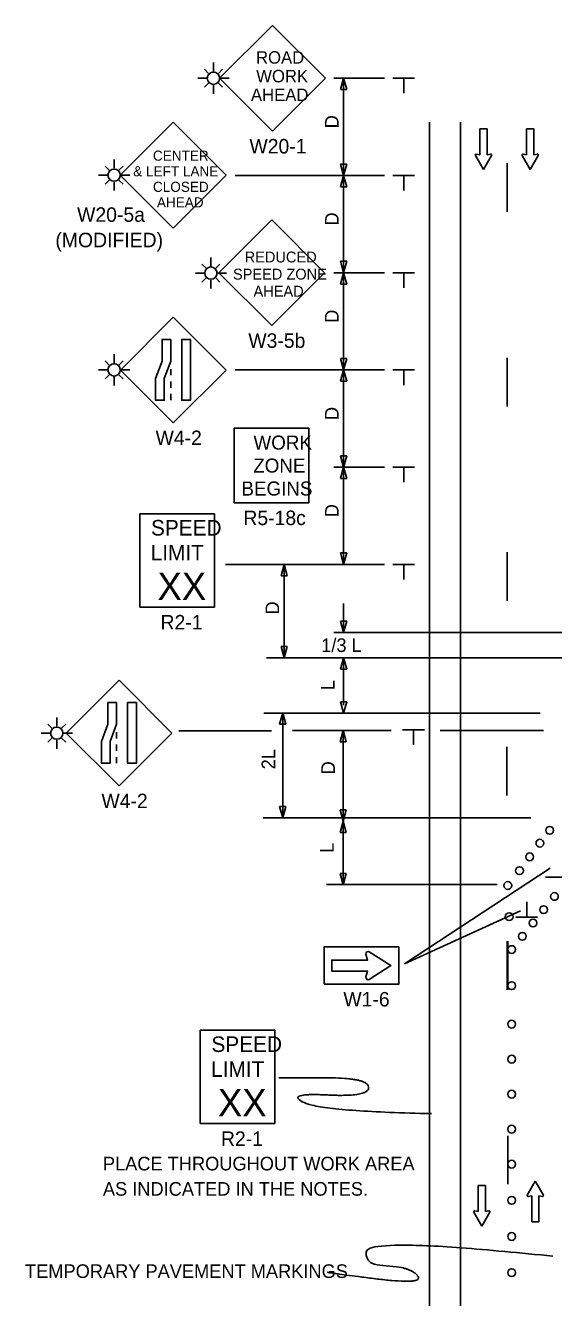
# Model space of a CAD drawing. Extents: x 16731 to 19504, y 5932 to 7446.
# Drawn here: x 16731 to 17002, y 6261 to 6915 of the extents above; entities that cross this region are included whole.
import ezdxf

# ---------------------------------------------------------------- set-up
doc = ezdxf.new("R2010")
doc.units = 0
for name, color, linetype in [('ALI_LEGAL_EX', 7, 'Continuous'), ('MT_SCRATCH_LEVEL_E', 7, 'Continuous'), ('PAVT_EDGE_EX', 7, 'Continuous'), ('TRAFFIC_SIGNS_PR', 7, 'Continuous'), ('TYPICAL_EX', 7, 'Continuous'), ('TYPICAL_TEXT_DIMEN_PR', 7, 'Continuous')]:
    doc.layers.add(name, color=color, linetype=linetype)

msp = doc.modelspace()

# ---------------------------------------------------------------- linework, layer by layer
at = {"layer": 'ALI_LEGAL_EX'}
for points in [[(16978.71, 6819.12), (16978.71, 6844.12)], [(16978.71, 6719.12), (16978.71, 6744.12)], [(16978.71, 6619.12), (16978.71, 6644.12)], [(16978.5, 6519.12), (16978.5, 6544.12)], [(16978.71, 6419.12), (16978.71, 6444.12)], [(16978.95, 6419.12), (16978.95, 6444.12)], [(16978.95, 6319.12), (16978.95, 6344.12)]]:
    msp.add_lwpolyline(points, dxfattribs=at)
at = {"layer": 'MT_SCRATCH_LEVEL_E'}
for p, q in [((16968.31, 6861.76), (16964.57, 6861.76)), ((16964.57, 6861.76), (16964.57, 6848.5)), ((16968.31, 6861.76), (16964.57, 6861.76)), ((16964.57, 6861.76), (16964.57, 6848.5)), ((16968.31, 6848.5), (16968.31, 6861.76)), ((16968.31, 6848.5), (16968.31, 6861.76)), ((16992.38, 6861.76), (16988.64, 6861.76)), ((16988.64, 6861.76), (16988.64, 6848.5)), ((16992.38, 6861.76), (16988.64, 6861.76)), ((16988.64, 6861.76), (16988.64, 6848.5)), ((16992.38, 6848.5), (16992.38, 6861.76)), ((16992.38, 6848.5), (16992.38, 6861.76)), ((16964.57, 6848.5), (16962.79, 6848.82)), ((16964.57, 6848.5), (16962.79, 6848.82)), ((16970.08, 6848.82), (16968.31, 6848.5)), ((16970.08, 6848.82), (16968.31, 6848.5)), ((16988.64, 6848.5), (16986.86, 6848.82)), ((16988.64, 6848.5), (16986.86, 6848.82)), ((16994.16, 6848.82), (16992.38, 6848.5)), ((16994.16, 6848.82), (16992.38, 6848.5)), ((16962.31, 6848.13), (16966.46, 6840.89)), ((16962.31, 6848.13), (16966.46, 6840.89)), ((16966.46, 6840.89), (16970.57, 6848.13)), ((16966.46, 6840.89), (16970.57, 6848.13)), ((16986.38, 6848.13), (16990.53, 6840.89)), ((16986.38, 6848.13), (16990.53, 6840.89)), ((16990.53, 6840.89), (16994.64, 6848.13)), ((16990.53, 6840.89), (16994.64, 6848.13)), ((16993.1, 6320.75), (16988.99, 6313.51)), ((16993.1, 6320.75), (16988.99, 6313.51)), ((16997.25, 6313.51), (16993.1, 6320.75)), ((16997.25, 6313.51), (16993.1, 6320.75)), ((16967.52, 6318.43), (16963.78, 6318.43)), ((16963.78, 6318.43), (16963.78, 6305.17)), ((16967.52, 6318.43), (16963.78, 6318.43)), ((16963.78, 6318.43), (16963.78, 6305.17)), ((16967.52, 6305.17), (16967.52, 6318.43)), ((16967.52, 6305.17), (16967.52, 6318.43)), ((16989.47, 6312.82), (16991.25, 6313.14)), ((16989.47, 6312.82), (16991.25, 6313.14)), ((16991.25, 6313.14), (16991.25, 6299.88)), ((16991.25, 6313.14), (16991.25, 6299.88)), ((16994.99, 6299.88), (16994.99, 6313.14)), ((16994.99, 6313.14), (16996.77, 6312.82)), ((16994.99, 6299.88), (16994.99, 6313.14)), ((16994.99, 6313.14), (16996.77, 6312.82)), ((16961.52, 6304.8), (16965.67, 6297.56)), ((16961.52, 6304.8), (16965.67, 6297.56)), ((16963.78, 6305.17), (16962, 6305.49)), ((16963.78, 6305.17), (16962, 6305.49)), ((16965.67, 6297.56), (16969.78, 6304.8)), ((16965.67, 6297.56), (16969.78, 6304.8)), ((16969.3, 6305.49), (16967.52, 6305.17)), ((16969.3, 6305.49), (16967.52, 6305.17)), ((16991.25, 6299.88), (16994.99, 6299.88)), ((16991.25, 6299.88), (16994.99, 6299.88))]:
    msp.add_line(p, q, dxfattribs=at)
for centre, start, end in [((16962.72, 6848.36), 80.03619, 209.77312), ((16962.72, 6848.36), 80.03619, 209.77312), ((16970.16, 6848.36), 330.42484, 99.96381), ((16970.16, 6848.36), 330.42484, 99.96381), ((16986.79, 6848.36), 80.03619, 209.77312), ((16986.79, 6848.36), 80.03619, 209.77312), ((16994.23, 6848.36), 330.42484, 99.96381), ((16994.23, 6848.36), 330.42484, 99.96381), ((16989.4, 6313.28), 150.42484, 279.96381), ((16989.4, 6313.28), 150.42484, 279.96381), ((16996.84, 6313.28), 260.03619, 29.77312), ((16996.84, 6313.28), 260.03619, 29.77312), ((16961.93, 6305.02), 80.03619, 209.77312), ((16961.93, 6305.02), 80.03619, 209.77312), ((16969.37, 6305.03), 330.42484, 99.96381), ((16969.37, 6305.03), 330.42484, 99.96381)]:
    msp.add_arc(centre, 0.463, start, end, dxfattribs=at)
at = {"layer": 'PAVT_EDGE_EX'}
for p, q in [((16954.71, 6865.32), (16954.71, 6079.93)), ((16938.71, 6770.67), (16938.71, 6079.72))]:
    msp.add_line(p, q, dxfattribs=at)
at = {"layer": 'TRAFFIC_SIGNS_PR'}
for p, q in [((16858.05, 6915), (16830.87, 6887.82)), ((16885.24, 6887.82), (16858.05, 6915)), ((16827.72, 6891.37), (16827.72, 6895.87)), ((16825.2, 6890.33), (16823.09, 6892.44)), ((16830.23, 6890.33), (16832.34, 6892.44)), ((16824.56, 6887.82), (16819.72, 6887.82)), ((16825.2, 6885.31), (16823.09, 6883.2)), ((16827.72, 6879.85), (16827.72, 6884.26)), ((16830.23, 6885.31), (16832.33, 6883.2)), ((16830.87, 6887.82), (16835.75, 6887.82)), ((16830.87, 6887.82), (16858.05, 6860.63)), ((16858.05, 6860.63), (16885.24, 6887.82)), ((16807.01, 6865.22), (16779.82, 6838.03)), ((16834.2, 6838.03), (16807.01, 6865.22)), ((16774.16, 6840.54), (16772.05, 6842.65)), ((16776.67, 6841.58), (16776.67, 6846.09)), ((16779.18, 6840.54), (16781.29, 6842.65)), ((16773.51, 6838.03), (16768.68, 6838.03)), ((16779.82, 6838.03), (16784.7, 6838.03)), ((16779.82, 6838.03), (16807.01, 6810.84)), ((16807.01, 6810.84), (16834.2, 6838.03)), ((16774.15, 6835.52), (16772.05, 6833.41)), ((16776.67, 6830.06), (16776.67, 6834.48)), ((16779.18, 6835.52), (16781.29, 6833.41)), ((16857.69, 6814.98), (16830.54, 6787.82)), ((16884.85, 6787.82), (16857.69, 6814.98)), ((16823.91, 6790.18), (16821.8, 6792.29)), ((16826.42, 6791.22), (16826.42, 6795.73)), ((16828.94, 6790.18), (16831.04, 6792.29)), ((16823.27, 6787.67), (16818.43, 6787.67)), ((16823.91, 6785.16), (16821.8, 6783.05)), ((16826.42, 6779.7), (16826.42, 6784.11)), ((16828.94, 6785.16), (16831.04, 6783.05)), ((16829.58, 6787.67), (16834.46, 6787.67)), ((16830.54, 6787.82), (16857.69, 6760.67)), ((16857.69, 6760.67), (16884.85, 6787.82)), ((16807.02, 6764.98), (16779.87, 6737.83)), ((16834.17, 6737.83), (16807.02, 6764.98)), ((16776.67, 6741.41), (16776.67, 6745.91)), ((16773.51, 6737.86), (16768.68, 6737.86)), ((16774.15, 6740.37), (16772.05, 6742.48)), ((16779.18, 6740.37), (16781.29, 6742.48)), ((16779.82, 6737.86), (16784.7, 6737.86)), ((16779.87, 6737.83), (16807.02, 6710.68)), ((16805.77, 6738.32), (16805.77, 6735.12)), ((16807.02, 6710.68), (16834.17, 6737.83)), ((16774.15, 6735.35), (16772.05, 6733.24)), ((16776.67, 6729.89), (16776.67, 6734.3)), ((16779.18, 6735.35), (16781.29, 6733.24)), ((16805.77, 6731.92), (16805.77, 6728.72)), ((16805.77, 6725.52), (16805.77, 6722.32)), ((16838.3, 6669.53), (16838.3, 6707.93)), ((16838.3, 6707.93), (16876.7, 6707.93)), ((16876.7, 6669.53), (16876.7, 6707.93)), ((16838.3, 6669.53), (16876.7, 6669.53)), ((16789.85, 6663.86), (16828.25, 6663.86)), ((16789.85, 6615.86), (16789.85, 6663.86)), ((16828.25, 6615.86), (16828.25, 6663.86)), ((16789.85, 6615.86), (16828.25, 6615.86)), ((16779.21, 6578.28), (16752.06, 6551.13)), ((16806.36, 6551.13), (16779.21, 6578.28)), ((16744.66, 6553.59), (16742.55, 6555.7)), ((16747.17, 6554.64), (16747.17, 6559.14)), ((16749.68, 6553.59), (16751.79, 6555.7)), ((16744.02, 6551.08), (16739.18, 6551.08)), ((16744.65, 6548.57), (16742.55, 6546.46)), ((16749.68, 6548.57), (16751.79, 6546.46)), ((16750.32, 6551.08), (16755.21, 6551.08)), ((16752.06, 6551.13), (16779.21, 6523.97)), ((16777.96, 6551.62), (16777.96, 6548.42)), ((16779.21, 6523.97), (16806.36, 6551.13)), ((16747.17, 6543.11), (16747.17, 6547.53)), ((16777.96, 6545.22), (16777.96, 6542.02)), ((16777.96, 6538.82), (16777.96, 6535.62)), ((16906.94, 6434.39), (16906.1, 6437.45)), ((16907.78, 6438.69), (16918.94, 6431.59)), ((16888.54, 6434.39), (16906.94, 6434.39)), ((16888.54, 6434.39), (16888.54, 6428.79)), ((16918.94, 6431.59), (16907.78, 6424.49)), ((16906.94, 6428.79), (16888.54, 6428.79)), ((16906.1, 6425.73), (16906.94, 6428.79)), ((16820.91, 6398.3), (16859.31, 6398.3)), ((16820.91, 6350.3), (16820.91, 6398.3)), ((16859.31, 6350.3), (16859.31, 6398.3)), ((16820.91, 6350.3), (16859.31, 6350.3))]:
    msp.add_line(p, q, dxfattribs=at)
for points in [[(16805.77, 6753.57), (16805.77, 6742.38), (16802.43, 6733.5), (16802.43, 6722.32), (16797.94, 6722.32), (16797.94, 6733.5), (16801.28, 6742.38), (16801.28, 6753.57)], [(16815.91, 6753.57), (16815.91, 6722.32), (16811.42, 6722.32), (16811.42, 6753.57)], [(16777.96, 6566.86), (16777.96, 6555.68), (16774.62, 6546.8), (16774.62, 6535.62), (16770.12, 6535.62), (16770.12, 6546.8), (16773.47, 6555.68), (16773.47, 6566.86)], [(16788.1, 6566.86), (16788.1, 6535.62), (16783.61, 6535.62), (16783.61, 6566.86)], [(16884.54, 6421.99), (16922.94, 6421.99), (16922.94, 6441.19), (16884.54, 6441.19)]]:
    msp.add_lwpolyline(points, close=True, dxfattribs=at)
for points in [[(16906.1, 6437.45), (16906.94, 6434.39), (16888.54, 6434.39), (16888.54, 6428.79), (16906.94, 6428.79), (16906.1, 6425.73)], [(16907.78, 6424.49), (16918.94, 6431.59), (16907.78, 6438.69)]]:
    msp.add_lwpolyline(points, dxfattribs=at)
for centre, radius in [((16827.71, 6887.82), 3.15), ((16776.67, 6838.03), 3.15), ((16826.42, 6787.67), 3.15), ((16776.67, 6737.86), 3.15), ((16747.17, 6551.08), 3.15), ((17000.47, 6501.15), 2), ((16995.48, 6494.51), 2), ((16990.19, 6487.48), 2), ((16984.99, 6480.37), 2), ((16978.97, 6472.76), 2), ((17002.95, 6467.14), 2), ((16979.71, 6456.72), 2), ((16997.45, 6460.31), 2), ((16991.95, 6453.48), 2), ((16986.45, 6446.65), 2), ((16980.95, 6439.82), 2), ((16980.95, 6439.82), 2), ((16980.95, 6421.23), 2), ((16980.95, 6401.47), 2), ((16980.95, 6383.47), 2), ((16980.95, 6365.47), 2), ((16980.95, 6347.47), 2), ((16980.95, 6329.47), 2), ((16980.95, 6310.89), 2), ((16980.95, 6292.3), 2), ((16980.95, 6273.71), 2)]:
    msp.add_circle(centre, radius, dxfattribs=at)
for centre, start, end in [((16907.18, 6437.74), 57.53038, 195.32692), ((16907.18, 6437.74), 57.53038, 195.32692), ((16907.18, 6425.43), 164.67308, 302.46962), ((16907.18, 6425.43), 164.67308, 302.46963)]:
    msp.add_arc(centre, 1.12, start, end, dxfattribs=at)
at = {"layer": 'TYPICAL_EX'}
msp.add_line((16938.71, 6865.32), (16938.71, 6080.34), dxfattribs=at)
at = {"layer": 'TYPICAL_TEXT_DIMEN_PR'}
for p, q in [((16889.61, 6887.88), (16915.61, 6887.88)), ((16893.04, 6882.02), (16894.61, 6887.88)), ((16894.61, 6882.02), (16893.04, 6882.02)), ((16894.61, 6837.88), (16894.61, 6887.88)), ((16894.61, 6887.88), (16896.18, 6882.02)), ((16896.18, 6882.02), (16894.61, 6882.02)), ((16919.86, 6887.88), (16931.11, 6887.88)), ((16925.49, 6887.88), (16925.49, 6880.1)), ((16894.61, 6837.88), (16893.04, 6843.74)), ((16893.04, 6843.74), (16894.61, 6843.74)), ((16894.61, 6843.74), (16896.18, 6843.74)), ((16896.18, 6843.74), (16894.61, 6837.88)), ((16838.81, 6837.88), (16915.61, 6837.88)), ((16889.61, 6837.88), (16915.61, 6837.88)), ((16893.04, 6832.02), (16894.61, 6837.88)), ((16894.61, 6787.88), (16894.61, 6837.88)), ((16894.61, 6837.88), (16896.18, 6832.02)), ((16919.86, 6837.88), (16931.11, 6837.88)), ((16925.49, 6837.88), (16925.49, 6830.1)), ((16894.61, 6832.02), (16893.04, 6832.02)), ((16896.18, 6832.02), (16894.61, 6832.02)), ((16894.61, 6787.88), (16893.04, 6793.74)), ((16893.04, 6793.74), (16894.61, 6793.74)), ((16894.61, 6793.74), (16896.18, 6793.74)), ((16896.18, 6793.74), (16894.61, 6787.88)), ((16889.61, 6787.88), (16915.61, 6787.88)), ((16889.61, 6787.88), (16915.61, 6787.88)), ((16893.04, 6782.02), (16894.61, 6787.88)), ((16894.61, 6787.88), (16896.18, 6782.02)), ((16894.61, 6737.88), (16894.61, 6787.88)), ((16919.86, 6787.88), (16931.11, 6787.88)), ((16925.49, 6787.88), (16925.49, 6780.1)), ((16894.61, 6782.02), (16893.04, 6782.02)), ((16896.18, 6782.02), (16894.61, 6782.02)), ((16838.81, 6737.88), (16915.61, 6737.88)), ((16894.61, 6737.88), (16893.04, 6743.74)), ((16893.04, 6743.74), (16894.61, 6743.74)), ((16893.04, 6732.02), (16894.61, 6737.88)), ((16894.61, 6743.74), (16896.18, 6743.74)), ((16896.18, 6743.74), (16894.61, 6737.88)), ((16894.61, 6737.88), (16896.18, 6732.02)), ((16894.61, 6687.88), (16894.61, 6737.88)), ((16919.86, 6737.88), (16931.11, 6737.88)), ((16925.49, 6737.88), (16925.49, 6730.1)), ((16894.61, 6732.02), (16893.04, 6732.02)), ((16896.18, 6732.02), (16894.61, 6732.02)), ((16894.61, 6687.88), (16893.04, 6693.74)), ((16893.04, 6693.74), (16894.61, 6693.74)), ((16894.61, 6693.74), (16896.18, 6693.74)), ((16896.18, 6693.74), (16894.61, 6687.88)), ((16889.61, 6687.88), (16915.61, 6687.88)), ((16893.04, 6682.02), (16894.61, 6687.88)), ((16894.61, 6687.88), (16896.18, 6682.02)), ((16894.61, 6637.88), (16894.61, 6687.88)), ((16919.86, 6687.88), (16931.11, 6687.88)), ((16925.49, 6687.88), (16925.49, 6680.1)), ((16894.61, 6682.02), (16893.04, 6682.02)), ((16896.18, 6682.02), (16894.61, 6682.02)), ((16894.61, 6637.88), (16893.04, 6643.74)), ((16893.04, 6643.74), (16894.61, 6643.74)), ((16894.61, 6643.74), (16896.18, 6643.74)), ((16896.18, 6643.74), (16894.61, 6637.88)), ((16833.96, 6637.88), (16915.61, 6637.88)), ((16862.46, 6632.02), (16864.03, 6637.88)), ((16864.03, 6637.88), (16865.6, 6632.02)), ((16864.03, 6590.05), (16864.03, 6637.88)), ((16919.86, 6637.88), (16931.11, 6637.88)), ((16925.49, 6637.88), (16925.49, 6630.1)), ((16864.03, 6632.02), (16862.46, 6632.02)), ((16865.6, 6632.02), (16864.03, 6632.02)), ((16894.61, 6617.73), (16894.61, 6602.8)), ((16894.61, 6602.8), (16893.04, 6608.67)), ((16893.04, 6608.67), (16894.61, 6608.67)), ((16894.61, 6608.67), (16896.18, 6608.67)), ((16896.18, 6608.67), (16894.61, 6602.8)), ((16889.61, 6602.8), (17039.81, 6602.8)), ((16864.03, 6589.79), (16862.46, 6595.65)), ((16862.46, 6595.65), (16864.03, 6595.65)), ((16864.03, 6595.65), (16865.6, 6595.65)), ((16865.6, 6595.65), (16864.03, 6589.79)), ((17018.77, 6589.8), (16854.92, 6589.8)), ((16893.04, 6584.03), (16894.61, 6589.9)), ((16894.61, 6589.9), (16896.18, 6584.03)), ((16894.61, 6565.46), (16894.61, 6589.57)), ((16894.61, 6584.03), (16893.04, 6584.03)), ((16896.18, 6584.03), (16894.61, 6584.03)), ((16853.65, 6561.39), (16995.64, 6561.39)), ((16861.73, 6555.76), (16863.3, 6561.62)), ((16863.3, 6561.62), (16864.87, 6555.76)), ((16863.3, 6507.59), (16863.3, 6561.55)), ((16894.61, 6561.36), (16893.04, 6567.22)), ((16893.04, 6567.22), (16894.61, 6567.22)), ((16894.61, 6567.22), (16896.18, 6567.22)), ((16896.18, 6567.22), (16894.61, 6561.36)), ((16863.3, 6555.76), (16861.73, 6555.76)), ((16864.87, 6555.76), (16863.3, 6555.76)), ((16809.87, 6552.3), (16857.58, 6552.3)), ((16868.33, 6552.45), (16919.09, 6552.45)), ((16892.84, 6546.61), (16894.41, 6552.47)), ((16894.4, 6505.69), (16894.4, 6552.03)), ((16894.41, 6552.47), (16895.98, 6546.61)), ((16924.9, 6552.86), (16936.15, 6552.86)), ((16930.52, 6552.86), (16930.52, 6545.08)), ((16944.17, 6552.45), (16997.31, 6552.45)), ((16894.41, 6546.61), (16892.84, 6546.61)), ((16895.98, 6546.61), (16894.41, 6546.61)), ((16863.3, 6507.59), (16861.73, 6513.45)), ((16861.73, 6513.45), (16863.3, 6513.45)), ((16863.3, 6513.45), (16864.87, 6513.45)), ((16864.87, 6513.45), (16863.3, 6507.59)), ((16894.42, 6505.78), (16892.85, 6511.65)), ((16892.85, 6511.65), (16894.42, 6511.65)), ((16894.42, 6511.65), (16895.99, 6511.65)), ((16895.99, 6511.65), (16894.42, 6505.78)), ((16853.25, 6507.59), (16990.78, 6507.59)), ((16892.84, 6499.97), (16894.41, 6505.83)), ((16894.4, 6473.12), (16894.4, 6505.4)), ((16894.41, 6505.83), (16895.98, 6499.97)), ((16894.41, 6499.97), (16892.84, 6499.97)), ((16895.98, 6499.97), (16894.41, 6499.97)), ((16894.41, 6473.11), (16892.84, 6478.97)), ((16892.84, 6478.97), (16894.41, 6478.97)), ((16894.41, 6478.97), (16895.98, 6478.97)), ((16895.98, 6478.97), (16894.41, 6473.11)), ((17000.78, 6481.68), (16925.85, 6432.51)), ((17009.64, 6477.01), (16998.39, 6477.01)), ((16885.76, 6473.24), (16973.48, 6473.24)), ((16988.71, 6456.51), (16988.71, 6464.29)), ((16925.85, 6432.51), (16985.56, 6459.73)), ((16994.33, 6456.51), (16983.08, 6456.51))]:
    msp.add_line(p, q, dxfattribs=at)
for points in [[(16939.73, 6355.46), (16882.33, 6356.68), (16864.97, 6366.15), (16907.5, 6363.95), (16907.5, 6373.86), (16863.85, 6373.86), (16861.33, 6373.86)], [(17002.21, 6282.17), (16908.69, 6291.94), (16904.45, 6277.62), (16928.94, 6276.71), (16936.35, 6267.32), (16884.59, 6273.89), (16886.54, 6273.89)]]:
    msp.add_open_spline(points, degree=2, dxfattribs=at)

# ---------------------------------------------------------------- texts
at = {"layer": 'TRAFFIC_SIGNS_PR'}
for s, height, p in [('ROAD', 6.408, (16849.59, 6895.36)), ('WORK', 6.408, (16849.69, 6885.75)), ('AHEAD', 6.408, (16847, 6876.14)), ('W20-1', 7.449, (16846.21, 6849.18)), ('CENTER', 5.206, (16796.63, 6845.44)), ('& LEFT LANE', 5.2065, (16786.49, 6837.43)), ('CLOSED', 5.206, (16796.63, 6829.42)), ('AHEAD', 5.206, (16798.66, 6821.41)), ('W20-5a', 7.449, (16757.65, 6814.02)), ('(MODIFIED)', 7.449, (16746.49, 6800.96)), ('REDUCED', 5.6, (16843.75, 6793.13)), ('SPEED ZONE', 5.6, (16837.74, 6784.33)), ('AHEAD', 5.6, (16848.3, 6775.53)), ('W3-5b', 7.44, (16845.65, 6749.23)), ('W4-2', 7.44, (16797.98, 6699.24)), ('WORK', 7.217, (16848.3, 6696.9)), ('ZONE', 7.217, (16848.18, 6685.09)), ('BEGINS', 7.217, (16842.11, 6673.28)), ('R5-18c', 7.44, (16843.11, 6658.09)), ('SPEED', 8, (16795.62, 6652.72)), ('LIMIT', 8, (16795.46, 6639.92)), ('XX', 14.031, (16798.96, 6619.61)), ('R2-1', 7.44, (16800.53, 6604.42)), ('W4-2', 7.44, (16770.17, 6512.53)), ('W1-6', 7.44, (16894.48, 6410.55)), ('SPEED', 8, (16826.68, 6387.16)), ('LIMIT', 8, (16826.52, 6374.36)), ('XX', 14.031, (16830.03, 6354.06)), ('R2-1', 7.44, (16831.59, 6338.86)), ('PLACE THROUGHOUT WORK AREA', 7, (16770.91, 6326.26)), ('AS INDICATED IN THE NOTES.', 7, (16770.91, 6313.26))]:
    msp.add_text(s, height=height, dxfattribs=at).set_placement(p)
at = {"layer": 'TYPICAL_TEXT_DIMEN_PR'}
for s, p in [('D', (16892.05, 6862.1)), ('D', (16892.05, 6812.1)), ('D', (16892.05, 6762.1)), ('D', (16892.05, 6712.1)), ('D', (16892.05, 6662.1)), ('D', (16861.47, 6612.1)), ('L', (16889.97, 6573.22)), ('2L', (16859.48, 6532.48)), ('D', (16890.15, 6529.91)), ('L', (16889.53, 6489.56))]:
    msp.add_text(s, height=7, rotation=90, dxfattribs=at).set_placement(p)
for s, p in [('1/3 L', (16883.1, 6592.83)), ('TEMPORARY PAVEMENT MARKINGS', (16730.9, 6270.96))]:
    msp.add_text(s, height=7, dxfattribs=at).set_placement(p)

doc.saveas('drawing.dxf')
